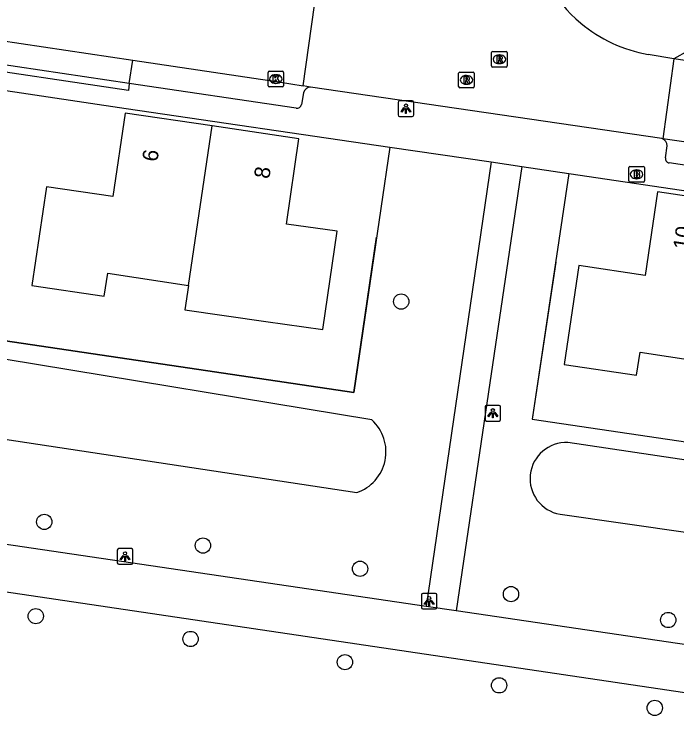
# Model space of a CAD drawing. Extents: x 164150 to 165261, y 382513 to 383432.
# Drawn here: x 164334.94 to 164377.35, y 383255.57 to 383301.75 of the extents above; entities that cross this region are included whole.
import ezdxf

# ---------------------------------------------------------------- set-up
doc = ezdxf.new("R2010")
doc.units = 0
for name, color, linetype in [('IMGEO_Boom', 7, 'Continuous'), ('IMGEO_Brandkraan', 7, 'Continuous'), ('IMGEO_Fietspad_gesloten', 7, 'Continuous'), ('IMGEO_Greppel_droge_sloot', 7, 'Continuous'), ('IMGEO_Groenvoorziening', 7, 'Continuous'), ('IMGEO_Hek', 7, 'Continuous'), ('IMGEO_Kolk', 7, 'Continuous'), ('IMGEO_Lichtpunt', 7, 'Continuous'), ('IMGEO_Pand', 7, 'Continuous'), ('IMGEO_Pand_nummerreeks', 7, 'Continuous'), ('IMGEO_Rijbaan_lokaal_open', 7, 'Continuous'), ('IMGEO_Rioolput', 7, 'Continuous'), ('IMGEO_Voetpad_gesloten', 7, 'Continuous'), ('IMGEO_Voetpad_open', 7, 'Continuous')]:
    doc.layers.add(name, color=color, linetype=linetype)

msp = doc.modelspace()

# ---------------------------------------------------------------- linework, layer by layer
at = {"layer": 'IMGEO_Boom'}
for centre in [(164359.713, 383283.357), (164336.852, 383269.25), (164347.015, 383267.738), (164357.078, 383266.248), (164366.746, 383264.626), (164336.308, 383263.214), (164376.82, 383262.968), (164346.222, 383261.753), (164356.111, 383260.27), (164365.986, 383258.785), (164375.956, 383257.337)]:
    msp.add_circle(centre, 0.489, dxfattribs=at)
at = {"layer": 'IMGEO_Brandkraan'}
for p, q in [((164374.288, 383291.082), (164374.288, 383291.934)), ((164374.363, 383292.008), (164375.215, 383292.008)), ((164374.776, 383291.788), (164374.801, 383291.788)), ((164375.289, 383291.934), (164375.289, 383291.082)), ((164374.799, 383291.228), (164374.774, 383291.228)), ((164375.215, 383291.008), (164374.363, 383291.008))]:
    msp.add_line(p, q, dxfattribs=at)
for points in [[(164374.288, 383291.082), (164374.288, 383291.934)], [(164374.363, 383292.008), (164375.215, 383292.008)], [(164374.636, 383291.708), (164374.636, 383291.308), (164374.849, 383291.308)], [(164374.867, 383291.708), (164374.636, 383291.708)], [(164375.289, 383291.934), (164375.289, 383291.082)], [(164374.815, 383291.627), (164374.761, 383291.627), (164374.761, 383291.551)], [(164374.761, 383291.551), (164374.814, 383291.551)], [(164374.823, 383291.475), (164374.761, 383291.475), (164374.761, 383291.394)], [(164374.761, 383291.394), (164374.823, 383291.394)], [(164375.215, 383291.008), (164374.363, 383291.008)]]:
    msp.add_lwpolyline(points, dxfattribs=at)
for centre, radius, start, end in [((164374.365, 383291.932), 0.0765, 91.552, 178.448), ((164374.365, 383291.932), 0.0765, 91.552, 178.448), ((164374.871, 383291.563), 0.145, 59.4692, 91.5367), ((164374.896, 383291.61), 0.0922, 285.5137, 58.1501), ((164375.213, 383291.932), 0.0765, 1.552, 88.448), ((164375.213, 383291.932), 0.0765, 1.552, 88.448), ((164374.816, 383291.589), 0.0379, 267.8285, 90.9355), ((164374.824, 383291.434), 0.0404, 269.8759, 90.5077), ((164374.855, 383291.559), 0.251, 268.6676, 293.5347), ((164374.901, 383291.418), 0.105, 301.3115, 78.989), ((164374.365, 383291.084), 0.0765, 181.552, 268.448), ((164374.365, 383291.084), 0.0765, 181.552, 268.448), ((164375.213, 383291.084), 0.0765, 271.552, 358.448), ((164375.213, 383291.084), 0.0765, 271.552, 358.448)]:
    msp.add_arc(centre, radius, start, end, dxfattribs=at)
for centre, major_axis, ratio, start_param, end_param in [((164374.775, 383291.508), (-0.387, 0.002), 0.722429, 4.712389, 7.853982), ((164374.8, 383291.508), (-0.39, 0.002), 0.717154, 1.570796, 4.712389)]:
    msp.add_ellipse(centre, major_axis=major_axis, ratio=ratio, start_param=start_param, end_param=end_param, dxfattribs=at)
at = {"layer": 'IMGEO_Fietspad_gesloten'}
for points in [[(164361.319, 383263.835), (164322.847, 383269.509), (164297.994, 383273.175)], [(164324.331, 383266.264), (164405.939, 383254.161)], [(164363.243, 383263.551), (164361.319, 383263.835)], [(164410.253, 383256.618), (164363.243, 383263.551)]]:
    msp.add_lwpolyline(points, dxfattribs=at)
at = {"layer": 'IMGEO_Greppel_droge_sloot'}
for points in [[(164357.836, 383275.781), (164310.701, 383283.555)], [(164309.922, 383278.25), (164356.862, 383271.129)], [(164369.89, 383269.745), (164406.61, 383264.48), (164406.724, 383268.924), (164370.391, 383274.325)]]:
    msp.add_lwpolyline(points, dxfattribs=at)
for centre, radius, start, end in [((164355.981, 383273.741), 2.757, 288.6381, 47.7112), ((164370.272, 383272.021), 2.307, 87.0523, 260.4623)]:
    msp.add_arc(centre, radius, start, end, dxfattribs=at)
at = {"layer": 'IMGEO_Groenvoorziening'}
for points in [[(164358.982, 383293.246), (164356.673, 383277.528), (164311.464, 383284.248), (164313.73, 383299.955)], [(164370.46, 383291.569), (164368.108, 383275.835), (164413.32, 383269.151), (164415.655, 383284.854)]]:
    msp.add_lwpolyline(points, dxfattribs=at)
at = {"layer": 'IMGEO_Hek'}
for points in [[(164312.911, 383294.277), (164311.464, 383284.248), (164356.673, 383277.528), (164358.137, 383287.492)], [(164369.61, 383285.882), (164368.108, 383275.835), (164413.32, 383269.151), (164414.814, 383279.195)]]:
    msp.add_lwpolyline(points, dxfattribs=at)
at = {"layer": 'IMGEO_Kolk'}
for p, q in [((164351.183, 383297.181), (164351.183, 383298.033)), ((164351.258, 383298.107), (164352.11, 383298.107)), ((164351.671, 383297.887), (164351.696, 383297.887)), ((164352.184, 383298.033), (164352.184, 383297.181)), ((164351.694, 383297.327), (164351.669, 383297.327)), ((164352.11, 383297.107), (164351.258, 383297.107))]:
    msp.add_line(p, q, dxfattribs=at)
for points in [[(164351.183, 383297.181), (164351.183, 383298.033)], [(164351.258, 383298.107), (164352.11, 383298.107)], [(164351.504, 383297.807), (164351.627, 383297.807), (164351.627, 383297.656), (164351.757, 383297.807), (164351.921, 383297.807), (164351.775, 383297.656), (164351.928, 383297.407), (164351.776, 383297.407), (164351.691, 383297.571), (164351.627, 383297.504), (164351.627, 383297.407), (164351.504, 383297.407), (164351.504, 383297.807)], [(164352.184, 383298.033), (164352.184, 383297.181)], [(164352.11, 383297.107), (164351.258, 383297.107)]]:
    msp.add_lwpolyline(points, dxfattribs=at)
for centre, start, end in [((164351.26, 383298.031), 91.552, 178.448), ((164351.26, 383298.031), 91.552, 178.448), ((164352.108, 383298.031), 1.552, 88.448), ((164352.108, 383298.031), 1.552, 88.448), ((164351.26, 383297.183), 181.552, 268.448), ((164351.26, 383297.183), 181.552, 268.448), ((164352.108, 383297.183), 271.552, 358.448), ((164352.108, 383297.183), 271.552, 358.448)]:
    msp.add_arc(centre, 0.0765, start, end, dxfattribs=at)
for centre, major_axis, ratio, start_param, end_param in [((164351.67, 383297.607), (-0.387, 0.002), 0.722429, 4.712389, 7.853982), ((164351.695, 383297.607), (-0.39, 0.002), 0.717154, 1.570796, 4.712389)]:
    msp.add_ellipse(centre, major_axis=major_axis, ratio=ratio, start_param=start_param, end_param=end_param, dxfattribs=at)
at = {"layer": 'IMGEO_Lichtpunt'}
for p, q in [((164359.518, 383296.115), (164359.518, 383295.308)), ((164359.518, 383296.115), (164359.518, 383295.308)), ((164360.42, 383296.21), (164359.612, 383296.21)), ((164360.42, 383296.21), (164359.612, 383296.21)), ((164360.514, 383295.308), (164360.514, 383296.115)), ((164360.514, 383295.308), (164360.514, 383296.115)), ((164359.612, 383295.214), (164360.42, 383295.214)), ((164359.612, 383295.214), (164360.42, 383295.214)), ((164365.084, 383276.611), (164365.084, 383275.804)), ((164365.084, 383276.611), (164365.084, 383275.804)), ((164365.986, 383276.706), (164365.178, 383276.706)), ((164365.986, 383276.706), (164365.178, 383276.706)), ((164366.08, 383275.804), (164366.08, 383276.611)), ((164366.08, 383275.804), (164366.08, 383276.611)), ((164365.178, 383275.71), (164365.986, 383275.71)), ((164365.178, 383275.71), (164365.986, 383275.71)), ((164341.527, 383267.445), (164341.527, 383266.638)), ((164341.527, 383267.445), (164341.527, 383266.638)), ((164342.429, 383267.54), (164341.621, 383267.54)), ((164342.429, 383267.54), (164341.621, 383267.54)), ((164342.523, 383266.638), (164342.523, 383267.445)), ((164342.523, 383266.638), (164342.523, 383267.445)), ((164341.621, 383266.544), (164342.429, 383266.544)), ((164341.621, 383266.544), (164342.429, 383266.544)), ((164361.006, 383264.578), (164361.006, 383263.771)), ((164361.006, 383264.578), (164361.006, 383263.771)), ((164361.908, 383264.673), (164361.1, 383264.673)), ((164361.908, 383264.673), (164361.1, 383264.673)), ((164362.002, 383263.771), (164362.002, 383264.578)), ((164362.002, 383263.771), (164362.002, 383264.578)), ((164361.1, 383263.677), (164361.908, 383263.677)), ((164361.1, 383263.677), (164361.908, 383263.677))]:
    msp.add_line(p, q, dxfattribs=at)
for points in [[(164359.892, 383295.779), (164359.931, 383295.751), (164359.743, 383295.489), (164359.705, 383295.516), (164359.892, 383295.779)], [(164359.994, 383295.731), (164360.041, 383295.731), (164360.041, 383295.409), (164359.994, 383295.409), (164359.994, 383295.731)], [(164360.104, 383295.751), (164360.142, 383295.778), (164360.329, 383295.516), (164360.29, 383295.488), (164360.104, 383295.751)], [(164365.458, 383276.275), (164365.497, 383276.247), (164365.309, 383275.985), (164365.271, 383276.012), (164365.458, 383276.275)], [(164365.56, 383276.227), (164365.607, 383276.227), (164365.607, 383275.905), (164365.56, 383275.905), (164365.56, 383276.227)], [(164365.67, 383276.247), (164365.708, 383276.274), (164365.895, 383276.012), (164365.856, 383275.984), (164365.67, 383276.247)], [(164341.901, 383267.109), (164341.94, 383267.081), (164341.752, 383266.819), (164341.714, 383266.846), (164341.901, 383267.109)], [(164342.003, 383267.061), (164342.05, 383267.061), (164342.05, 383266.739), (164342.003, 383266.739), (164342.003, 383267.061)], [(164342.113, 383267.081), (164342.151, 383267.108), (164342.338, 383266.846), (164342.299, 383266.818), (164342.113, 383267.081)], [(164361.38, 383264.242), (164361.419, 383264.214), (164361.231, 383263.952), (164361.193, 383263.979), (164361.38, 383264.242)], [(164361.482, 383264.194), (164361.529, 383264.194), (164361.529, 383263.872), (164361.482, 383263.872), (164361.482, 383264.194)], [(164361.592, 383264.214), (164361.63, 383264.241), (164361.817, 383263.979), (164361.778, 383263.951), (164361.592, 383264.214)]]:
    msp.add_lwpolyline(points, dxfattribs=at)
for centre in [(164360.017, 383295.913), (164365.583, 383276.409), (164342.026, 383267.243), (164361.505, 383264.376)]:
    msp.add_circle(centre, 0.0994, dxfattribs=at)
for centre, start, end in [((164359.612, 383296.115), 90, 180), ((164359.612, 383296.115), 90, 180), ((164360.42, 383296.115), 0, 90), ((164360.42, 383296.115), 0, 90), ((164359.612, 383295.308), 180, 270), ((164359.612, 383295.308), 180, 270), ((164360.42, 383295.308), 270, 0), ((164360.42, 383295.308), 270, 360), ((164365.178, 383276.611), 90, 180), ((164365.178, 383276.611), 90, 180), ((164365.986, 383276.611), 0, 90), ((164365.986, 383276.611), 0, 90), ((164365.178, 383275.804), 180, 270), ((164365.178, 383275.804), 180, 270), ((164365.986, 383275.804), 270, 0), ((164365.986, 383275.804), 270, 360), ((164341.621, 383267.445), 90, 180), ((164341.621, 383267.445), 90, 180), ((164342.429, 383267.445), 0, 90), ((164342.429, 383267.445), 0, 90), ((164341.621, 383266.638), 180, 270), ((164341.621, 383266.638), 180, 270), ((164342.429, 383266.638), 270, 0), ((164342.429, 383266.638), 270, 360), ((164361.1, 383264.578), 90, 180), ((164361.1, 383264.578), 90, 180), ((164361.908, 383264.578), 0, 90), ((164361.908, 383264.578), 0, 90), ((164361.1, 383263.771), 180, 270), ((164361.1, 383263.771), 180, 270), ((164361.908, 383263.771), 270, 0), ((164361.908, 383263.771), 270, 360)]:
    msp.add_arc(centre, 0.0946, start, end, dxfattribs=at)
at = {"layer": 'IMGEO_Pand'}
for points in [[(164347.6, 383294.601), (164342.038, 383295.429), (164341.239, 383290.078), (164336.997, 383290.713), (164336.057, 383284.386), (164340.696, 383283.697), (164340.917, 383285.18), (164346.079, 383284.379)], [(164346.079, 383284.379), (164345.85, 383282.839), (164351.032, 383282.092), (164354.703, 383281.563), (164355.607, 383287.863), (164352.356, 383288.323), (164353.163, 383293.772), (164347.6, 383294.601)], [(164346.079, 383284.379), (164347.6, 383294.601)], [(164381.713, 383289.549), (164376.135, 383290.377), (164375.336, 383285.025), (164371.093, 383285.661), (164370.154, 383279.333), (164374.793, 383278.644), (164375.013, 383280.128), (164380.196, 383279.324)]]:
    msp.add_lwpolyline(points, dxfattribs=at)
at = {"layer": 'IMGEO_Rijbaan_lokaal_open'}
for points in [[(164353.437, 383297.172), (164354.167, 383302.338)], [(164331.054, 383300.519), (164342.533, 383298.815)], [(164377.184, 383298.907), (164375.526, 383299.185)], [(164342.299, 383297.318), (164330.829, 383299.025)], [(164342.299, 383297.318), (164342.533, 383298.815)], [(164342.533, 383298.815), (164351.856, 383297.431), (164353.437, 383297.172)], [(164377.184, 383298.907), (164376.462, 383293.782)], [(164416.301, 383293.154), (164377.184, 383298.907)], [(164353.906, 383297.096), (164353.437, 383297.172)], [(164376.405, 383293.791), (164353.906, 383297.096)], [(164376.462, 383293.782), (164376.405, 383293.791)], [(164387.772, 383292.123), (164381.386, 383293.071), (164376.462, 383293.782)]]:
    msp.add_lwpolyline(points, dxfattribs=at)
for centre, radius, start, end in [((164375.362, 383306.442), 6.692, 174.7992, 231.6593), ((164377.1, 383308.203), 9.155, 229.9663, 260.1017)]:
    msp.add_arc(centre, radius, start, end, dxfattribs=at)
at = {"layer": 'IMGEO_Rioolput'}
for p, q in [((164365.504, 383298.447), (164365.504, 383299.299)), ((164365.579, 383299.373), (164366.431, 383299.373)), ((164365.992, 383299.153), (164366.017, 383299.153)), ((164366.505, 383299.299), (164366.505, 383298.447)), ((164366.431, 383298.373), (164365.579, 383298.373)), ((164366.015, 383298.593), (164365.99, 383298.593)), ((164363.393, 383297.128), (164363.393, 383297.98)), ((164363.468, 383298.054), (164364.32, 383298.054)), ((164363.881, 383297.834), (164363.906, 383297.834)), ((164364.394, 383297.98), (164364.394, 383297.128)), ((164363.904, 383297.274), (164363.879, 383297.274)), ((164364.32, 383297.054), (164363.468, 383297.054))]:
    msp.add_line(p, q, dxfattribs=at)
for points in [[(164365.504, 383298.447), (164365.504, 383299.299)], [(164365.579, 383299.373), (164366.431, 383299.373)], [(164366.093, 383299.071), (164365.841, 383299.073), (164365.841, 383298.673)], [(164366.505, 383299.299), (164366.505, 383298.447)], [(164365.841, 383298.673), (164365.965, 383298.673), (164365.965, 383298.835), (164365.976, 383298.835)], [(164366.019, 383298.992), (164365.965, 383298.992), (164365.965, 383298.911)], [(164365.965, 383298.911), (164366.017, 383298.911)], [(164366.023, 383298.806), (164366.094, 383298.673), (164366.234, 383298.673), (164366.169, 383298.799)], [(164366.431, 383298.373), (164365.579, 383298.373)], [(164363.393, 383297.128), (164363.393, 383297.98)], [(164363.468, 383298.054), (164364.32, 383298.054)], [(164363.982, 383297.752), (164363.73, 383297.754), (164363.73, 383297.354)], [(164363.908, 383297.673), (164363.854, 383297.673), (164363.854, 383297.592)], [(164364.394, 383297.98), (164364.394, 383297.128)], [(164363.73, 383297.354), (164363.854, 383297.354), (164363.854, 383297.516), (164363.865, 383297.516)], [(164363.854, 383297.592), (164363.906, 383297.592)], [(164363.912, 383297.487), (164363.983, 383297.354), (164364.123, 383297.354), (164364.058, 383297.48)], [(164364.32, 383297.054), (164363.468, 383297.054)]]:
    msp.add_lwpolyline(points, dxfattribs=at)
for centre, radius, start, end in [((164365.581, 383299.297), 0.0765, 91.552, 178.448), ((164365.581, 383299.297), 0.0765, 91.552, 178.448), ((164366.092, 383298.961), 0.109, 350.3612, 89.416), ((164366.429, 383299.297), 0.0765, 1.552, 88.448), ((164366.429, 383299.297), 0.0765, 1.552, 88.448), ((164365.975, 383298.782), 0.0533, 26.0293, 88.6989), ((164366.001, 383299.1), 0.19, 274.7715, 282.9687), ((164366.025, 383298.896), 0.0964, 77.0061, 93.1865), ((164366.039, 383298.953), 0.0378, 276.6634, 79.6772), ((164366.09, 383298.961), 0.112, 277.5842, 350.9817), ((164366.074, 383298.746), 0.108, 29.5134, 73.7905), ((164365.581, 383298.449), 0.0765, 181.552, 268.448), ((164365.581, 383298.449), 0.0765, 181.552, 268.448), ((164366.429, 383298.449), 0.0765, 271.552, 358.448), ((164366.429, 383298.449), 0.0765, 271.552, 358.448), ((164363.47, 383297.978), 0.0765, 91.552, 178.448), ((164363.47, 383297.978), 0.0765, 91.552, 178.448), ((164363.914, 383297.577), 0.0964, 77.0061, 93.1865), ((164363.981, 383297.642), 0.109, 350.3612, 89.416), ((164364.318, 383297.978), 0.0765, 1.552, 88.448), ((164364.318, 383297.978), 0.0765, 1.552, 88.448), ((164363.864, 383297.463), 0.0533, 26.0293, 88.6989), ((164363.89, 383297.781), 0.19, 274.7715, 282.9687), ((164363.928, 383297.634), 0.0378, 276.6634, 79.6772), ((164363.979, 383297.642), 0.112, 277.5842, 350.9817), ((164363.963, 383297.427), 0.108, 29.5134, 73.7905), ((164363.47, 383297.13), 0.0765, 181.552, 268.448), ((164363.47, 383297.13), 0.0765, 181.552, 268.448), ((164364.318, 383297.13), 0.0765, 271.552, 358.448), ((164364.318, 383297.13), 0.0765, 271.552, 358.448)]:
    msp.add_arc(centre, radius, start, end, dxfattribs=at)
for centre, major_axis, ratio, start_param, end_param in [((164365.991, 383298.873), (-0.387, 0.002), 0.722429, 4.712389, 7.853982), ((164366.016, 383298.873), (-0.39, 0.002), 0.717154, 1.570796, 4.712389), ((164363.88, 383297.554), (-0.387, 0.002), 0.722429, 4.712389, 7.853982), ((164363.905, 383297.554), (-0.39, 0.002), 0.717154, 1.570796, 4.712389)]:
    msp.add_ellipse(centre, major_axis=major_axis, ratio=ratio, start_param=start_param, end_param=end_param, dxfattribs=at)
at = {"layer": 'IMGEO_Voetpad_gesloten'}
for points in [[(164365.477, 383292.297), (164361.319, 383263.835)], [(164365.477, 383292.297), (164367.432, 383292.011)], [(164367.432, 383292.011), (164365.396, 383278.153), (164363.243, 383263.551)]]:
    msp.add_lwpolyline(points, dxfattribs=at)
at = {"layer": 'IMGEO_Voetpad_open'}
for points in [[(164379.143, 383300.167), (164378.103, 383299.409), (164377.184, 383298.907)], [(164313.73, 383299.955), (164319.528, 383299.102), (164342.102, 383295.732), (164358.982, 383293.246)], [(164342.299, 383297.318), (164342.238, 383296.879), (164330.761, 383298.586), (164330.829, 383299.025)], [(164352.979, 383295.744), (164342.299, 383297.318)], [(164353.451, 383296.731), (164353.318, 383295.982)], [(164358.982, 383293.246), (164365.477, 383292.297)], [(164376.634, 383292.569), (164376.75, 383293.324)], [(164387.523, 383290.657), (164381.248, 383291.584), (164376.884, 383292.237)], [(164367.432, 383292.011), (164370.46, 383291.569)], [(164370.46, 383291.569), (164381.278, 383289.967), (164387.313, 383289.078), (164406.647, 383286.21), (164415.655, 383284.854)]]:
    msp.add_lwpolyline(points, dxfattribs=at)
for centre, radius, start, end in [((164353.972, 383296.547), 0.553, 96.8753, 160.5977), ((164353.039, 383296.019), 0.281, 257.6337, 352.5089), ((164376.267, 383293.328), 0.483, 359.5371, 73.3738), ((164376.924, 383292.528), 0.293, 171.8817, 262.0787)]:
    msp.add_arc(centre, radius, start, end, dxfattribs=at)

# ---------------------------------------------------------------- texts
at = {"layer": 'IMGEO_Pand_nummerreeks'}
for s, rotation, p in [('6', 81.5122, (164344.095, 383292.277)), ('8', 81.572, (164351.263, 383291.184)), ('10', 81.5122, (164378.104, 383286.634))]:
    msp.add_text(s, height=1, rotation=rotation, dxfattribs=at).set_placement(p)

doc.saveas('drawing.dxf')
